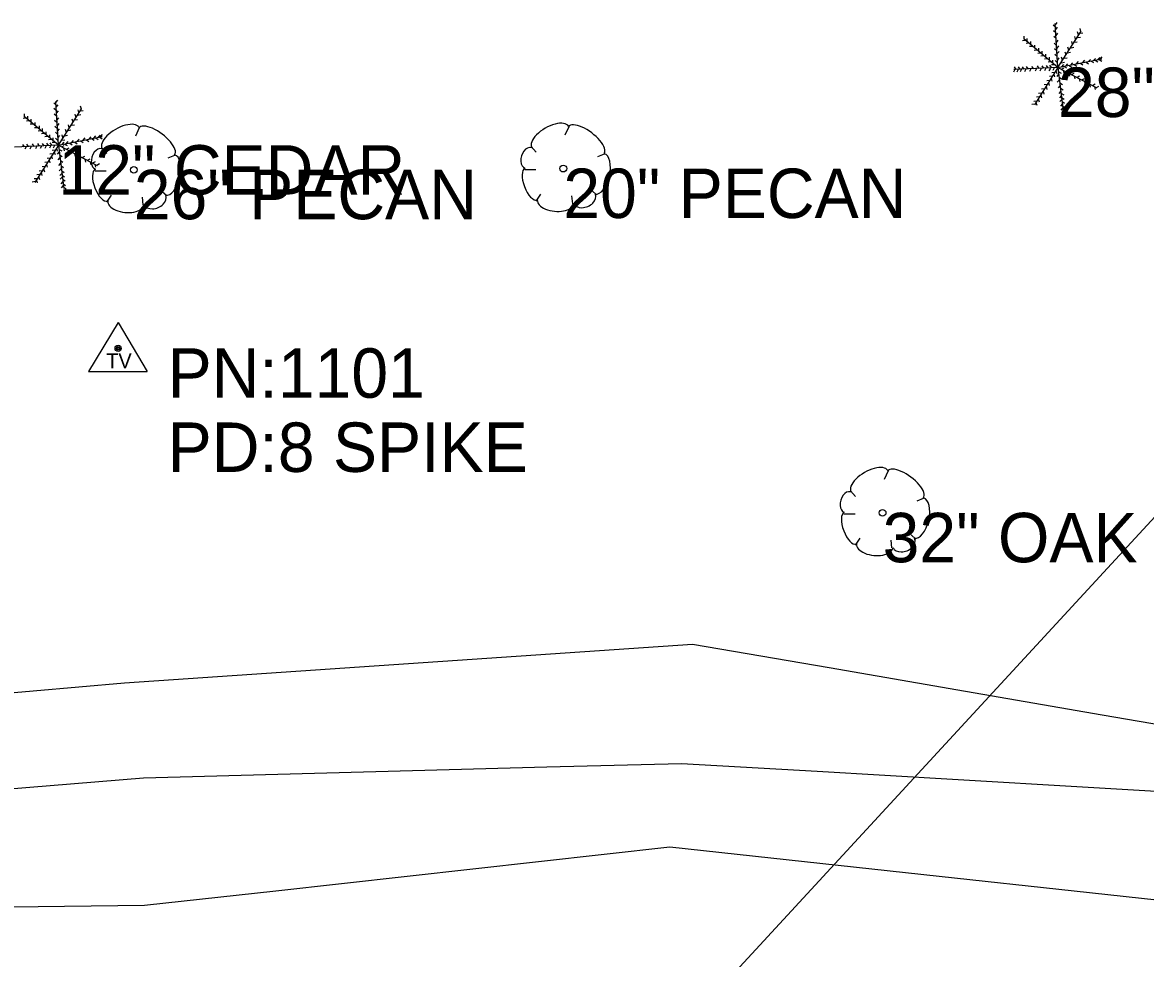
# Model space of a CAD drawing. Extents: x 1930288 to 1941089, y 588389 to 611475.
# Drawn here: x 1930644.9 to 1930758.4, y 598182.1 to 598276.8 of the extents above; entities that cross this region are included whole.
import ezdxf

# ---------------------------------------------------------------- set-up
doc = ezdxf.new("R2010")
doc.units = 0
for name, color, linetype in [('S_DITCHLINE', 7, 'Continuous'), ('S_GAS_UTILITIES', 7, 'Continuous'), ('S_SECONDARY_CTL', 7, 'Continuous'), ('S_SECONDARY_CTL_ANNOT', 7, 'Continuous'), ('S_STREAM', 7, 'Continuous'), ('S_TREE', 7, 'Continuous'), ('S_TREE_ANNOT', 7, 'Continuous')]:
    doc.layers.add(name, color=color, linetype=linetype)

msp = doc.modelspace()

# ---------------------------------------------------------------- linework, layer by layer
at = {"layer": 'S_DITCHLINE'}
msp.add_lwpolyline([(1930873.87, 598182.1), (1930857.41, 598182.4), (1930840.53, 598182.46), (1930823.65, 598182.52), (1930809.32, 598186.54), (1930794.99, 598190.57), (1930780.66, 598194.59), (1930766.34, 598198.62), (1930752.63, 598199.42), (1930738.92, 598200.23), (1930725.22, 598201.03), (1930711.51, 598201.83), (1930697.9, 598201.47), (1930684.3, 598201.1), (1930670.69, 598200.73), (1930657.08, 598200.36), (1930638.19, 598198.83)], dxfattribs=at)
at = {"layer": 'S_GAS_UTILITIES'}
msp.add_line((1930763.56, 598231.34), (1930683.07, 598144.05), dxfattribs=at)
at = {"layer": 'S_SECONDARY_CTL'}
for p, q in [((1930654.53, 598246.45), (1930651.52, 598241.49)), ((1930654.53, 598246.45), (1930657.48, 598241.49)), ((1930651.52, 598241.49), (1930657.48, 598241.49))]:
    msp.add_line(p, q, dxfattribs=at)
for radius in [0.311, 0.183, 0.103]:
    msp.add_circle((1930654.53, 598243.84), radius, dxfattribs=at)
at = {"layer": 'S_STREAM'}
for points in [[(1930906.83, 598185.8), (1930890.27, 598187.32), (1930874.15, 598188.74), (1930858.02, 598190.16), (1930839.57, 598191.65), (1930821.12, 598193.14), (1930807.8, 598195.95), (1930794.49, 598198.75), (1930781.17, 598201.56), (1930767.85, 598204.36), (1930754.04, 598206.75), (1930740.24, 598209.13), (1930726.43, 598211.51), (1930712.62, 598213.9), (1930698.26, 598212.92), (1930683.89, 598211.94), (1930669.53, 598210.96), (1930655.17, 598209.99), (1930636.67, 598208.34)], [(1930795.11, 598181.46), (1930779.97, 598184.46), (1930764.83, 598187.45), (1930751.2, 598188.94), (1930737.57, 598190.42), (1930723.94, 598191.9), (1930710.31, 598193.39), (1930697.04, 598191.91), (1930683.76, 598190.43), (1930670.49, 598188.95), (1930657.21, 598187.47), (1930638.3, 598187.25)]]:
    msp.add_lwpolyline(points, dxfattribs=at)
at = {"layer": 'S_TREE'}
for p, q in [((1930749.33, 598276.32), (1930749.1, 598276.52)), ((1930749.58, 598272.24), (1930749.31, 598276.68)), ((1930749.32, 598276.57), (1930749.51, 598276.8)), ((1930749.35, 598276.09), (1930749.54, 598276.32)), ((1930749.58, 598272.24), (1930746.12, 598275.15)), ((1930746.15, 598275.12), (1930746.15, 598275.42)), ((1930746.47, 598274.87), (1930746.47, 598275.17)), ((1930749.36, 598275.76), (1930749.13, 598275.96)), ((1930749.39, 598275.18), (1930749.16, 598275.38)), ((1930749.38, 598275.49), (1930749.57, 598275.72)), ((1930749.58, 598272.24), (1930751.92, 598275.92)), ((1930751.35, 598275.1), (1930751.27, 598275.39)), ((1930751.54, 598275.29), (1930751.84, 598275.33)), ((1930751.65, 598275.55), (1930751.56, 598275.84)), ((1930751.79, 598275.71), (1930752.08, 598275.76)), ((1930751.9, 598275.89), (1930751.81, 598276.18)), ((1930746.3, 598274.98), (1930746, 598274.94)), ((1930746.64, 598274.71), (1930746.35, 598274.68)), ((1930747.01, 598274.38), (1930746.71, 598274.36)), ((1930746.83, 598274.58), (1930746.83, 598274.88)), ((1930747.46, 598274.01), (1930747.16, 598273.98)), ((1930747.24, 598274.22), (1930747.24, 598274.52)), ((1930747.65, 598273.89), (1930747.65, 598274.19)), ((1930749.41, 598274.52), (1930749.19, 598274.72)), ((1930749.45, 598273.93), (1930749.23, 598274.13)), ((1930749.42, 598274.78), (1930749.61, 598275.01)), ((1930749.49, 598274.21), (1930749.68, 598274.45)), ((1930750.68, 598274.01), (1930750.59, 598274.3)), ((1930750.9, 598274.25), (1930751.19, 598274.3)), ((1930751.06, 598274.58), (1930750.97, 598274.87)), ((1930751.22, 598274.8), (1930751.52, 598274.84)), ((1930747.83, 598273.68), (1930747.53, 598273.66)), ((1930748.16, 598273.41), (1930747.86, 598273.39)), ((1930747.97, 598273.61), (1930747.97, 598273.91)), ((1930748.5, 598273.12), (1930748.2, 598273.09)), ((1930748.34, 598273.31), (1930748.34, 598273.61)), ((1930748.71, 598273), (1930748.71, 598273.3)), ((1930749.06, 598272.69), (1930749.06, 598272.99)), ((1930749.49, 598273.36), (1930749.27, 598273.56)), ((1930749.5, 598272.74), (1930749.28, 598272.94)), ((1930749.5, 598273.65), (1930749.69, 598273.88)), ((1930749.53, 598272.97), (1930749.71, 598273.21)), ((1930749.58, 598272.24), (1930754, 598273.11)), ((1930750.03, 598273), (1930749.94, 598273.28)), ((1930750.21, 598273.2), (1930750.51, 598273.24)), ((1930750.39, 598273.52), (1930750.3, 598273.81)), ((1930750.55, 598273.74), (1930750.84, 598273.78)), ((1930752.09, 598272.76), (1930752.29, 598272.98)), ((1930752.68, 598272.85), (1930752.88, 598273.07)), ((1930752.93, 598272.9), (1930753.18, 598272.74)), ((1930753.16, 598272.95), (1930753.36, 598273.17)), ((1930753.35, 598272.99), (1930753.61, 598272.83)), ((1930753.61, 598273.04), (1930753.81, 598273.26)), ((1930753.76, 598273.05), (1930754.01, 598272.89)), ((1930753.83, 598273.09), (1930754.04, 598273.32)), ((1930745.21, 598272.03), (1930745.08, 598271.76)), ((1930749.58, 598272.24), (1930745.13, 598272.03)), ((1930745.36, 598272.05), (1930745.19, 598272.3)), ((1930745.56, 598272.05), (1930745.43, 598271.79)), ((1930745.75, 598272.08), (1930745.58, 598272.33)), ((1930745.9, 598272.07), (1930745.77, 598271.8)), ((1930746.15, 598272.08), (1930745.98, 598272.33)), ((1930746.32, 598272.09), (1930746.19, 598271.82)), ((1930746.55, 598272.1), (1930746.38, 598272.35)), ((1930746.83, 598272.11), (1930746.7, 598271.84)), ((1930747.12, 598272.12), (1930746.95, 598272.36)), ((1930749.58, 598272.24), (1930747.2, 598268.47)), ((1930747.39, 598272.14), (1930747.26, 598271.87)), ((1930747.67, 598272.15), (1930747.5, 598272.4)), ((1930747.88, 598272.16), (1930747.74, 598271.89)), ((1930748.15, 598272.17), (1930747.98, 598272.42)), ((1930748.35, 598272.18), (1930748.21, 598271.91)), ((1930748.59, 598272.21), (1930748.42, 598272.45)), ((1930748.87, 598272.82), (1930748.57, 598272.8)), ((1930748.81, 598272.19), (1930748.67, 598271.92)), ((1930748.92, 598272.24), (1930748.75, 598272.49)), ((1930749.23, 598272.52), (1930748.93, 598272.5)), ((1930749.25, 598271.74), (1930748.95, 598271.71)), ((1930749.19, 598272.2), (1930749.06, 598271.93)), ((1930749.37, 598271.92), (1930749.45, 598271.63)), ((1930749.58, 598272.24), (1930753.5, 598270.2)), ((1930749.58, 598272.24), (1930750.11, 598267.87)), ((1930749.66, 598271.81), (1930749.91, 598271.66)), ((1930749.91, 598272.06), (1930750.17, 598272.2)), ((1930749.93, 598272.73), (1930750.23, 598272.77)), ((1930749.96, 598272.33), (1930750.16, 598272.55)), ((1930750.09, 598271.96), (1930750.16, 598271.67)), ((1930750.2, 598272.36), (1930750.45, 598272.2)), ((1930750.36, 598272.38), (1930750.56, 598272.61)), ((1930750.39, 598271.83), (1930750.65, 598271.97)), ((1930750.72, 598272.43), (1930750.97, 598272.27)), ((1930750.89, 598272.49), (1930751.09, 598272.71)), ((1930751.23, 598272.55), (1930751.49, 598272.39)), ((1930751.45, 598272.62), (1930751.66, 598272.84)), ((1930751.84, 598272.68), (1930752.09, 598272.52)), ((1930752.42, 598272.78), (1930752.67, 598272.62)), ((1930748.73, 598270.93), (1930748.44, 598270.9)), ((1930748.63, 598270.73), (1930748.7, 598270.44)), ((1930749.01, 598271.38), (1930748.71, 598271.34)), ((1930748.88, 598271.14), (1930748.96, 598270.85)), ((1930749.16, 598271.58), (1930749.24, 598271.29)), ((1930749.64, 598271.56), (1930749.45, 598271.34)), ((1930749.71, 598270.98), (1930749.51, 598270.76)), ((1930749.7, 598271.26), (1930749.95, 598271.1)), ((1930749.78, 598270.69), (1930750.04, 598270.54)), ((1930750.67, 598271.66), (1930750.74, 598271.37)), ((1930750.94, 598271.53), (1930751.21, 598271.67)), ((1930751.21, 598271.38), (1930751.28, 598271.09)), ((1930751.5, 598271.25), (1930751.76, 598271.39)), ((1930751.73, 598271.11), (1930751.8, 598270.82)), ((1930751.98, 598270.99), (1930752.25, 598271.13)), ((1930752.26, 598270.81), (1930752.33, 598270.52)), ((1930752.52, 598270.72), (1930752.78, 598270.86)), ((1930747.92, 598269.64), (1930747.62, 598269.61)), ((1930747.84, 598269.46), (1930747.91, 598269.17)), ((1930748.22, 598270.09), (1930747.92, 598270.06)), ((1930748.08, 598269.84), (1930748.16, 598269.55)), ((1930748.48, 598270.51), (1930748.19, 598270.48)), ((1930748.37, 598270.31), (1930748.44, 598270.01)), ((1930749.79, 598270.42), (1930749.59, 598270.2)), ((1930749.86, 598269.85), (1930749.67, 598269.63)), ((1930749.84, 598270.14), (1930750.1, 598269.99)), ((1930749.92, 598269.63), (1930750.17, 598269.48)), ((1930752.78, 598270.56), (1930752.85, 598270.27)), ((1930753.06, 598270.44), (1930753.33, 598270.58)), ((1930753.27, 598270.31), (1930753.34, 598270.01)), ((1930753.46, 598270.23), (1930753.72, 598270.37)), ((1930648.24, 598268.47), (1930648.01, 598268.67)), ((1930648.49, 598264.39), (1930648.22, 598268.82)), ((1930648.23, 598268.72), (1930648.42, 598268.95)), ((1930648.26, 598268.24), (1930648.45, 598268.47)), ((1930650.81, 598268.04), (1930650.72, 598268.33)), ((1930747.23, 598268.55), (1930746.93, 598268.52)), ((1930747.43, 598268.85), (1930747.13, 598268.82)), ((1930747.35, 598268.71), (1930747.43, 598268.42)), ((1930747.68, 598269.27), (1930747.39, 598269.23)), ((1930747.58, 598269.06), (1930747.66, 598268.77)), ((1930749.93, 598269.4), (1930749.73, 598269.17)), ((1930749.96, 598269.02), (1930749.77, 598268.79)), ((1930750.02, 598268.57), (1930749.83, 598268.34)), ((1930749.95, 598269.2), (1930750.2, 598269.05)), ((1930749.99, 598268.8), (1930750.25, 598268.64)), ((1930750.06, 598268.33), (1930750.31, 598268.17)), ((1930648.49, 598264.39), (1930645.03, 598267.3)), ((1930645.06, 598267.27), (1930645.06, 598267.57)), ((1930645.38, 598267.02), (1930645.38, 598267.32)), ((1930648.27, 598267.9), (1930648.04, 598268.1)), ((1930648.3, 598267.33), (1930648.07, 598267.53)), ((1930648.29, 598267.64), (1930648.48, 598267.87)), ((1930648.49, 598264.39), (1930650.83, 598268.07)), ((1930650.26, 598267.25), (1930650.18, 598267.53)), ((1930650.45, 598267.43), (1930650.75, 598267.48)), ((1930650.56, 598267.7), (1930650.47, 598267.98)), ((1930650.7, 598267.86), (1930650.99, 598267.9)), ((1930750.07, 598268.15), (1930749.87, 598267.92)), ((1930750.1, 598267.99), (1930750.35, 598267.83)), ((1930645.21, 598267.13), (1930644.91, 598267.09)), ((1930645.55, 598266.85), (1930645.26, 598266.83)), ((1930645.92, 598266.53), (1930645.62, 598266.51)), ((1930645.74, 598266.73), (1930645.74, 598267.03)), ((1930646.37, 598266.16), (1930646.07, 598266.13)), ((1930646.15, 598266.37), (1930646.15, 598266.67)), ((1930646.56, 598266.04), (1930646.56, 598266.34)), ((1930646.88, 598265.76), (1930646.88, 598266.06)), ((1930648.32, 598266.67), (1930648.1, 598266.87)), ((1930648.36, 598266.08), (1930648.14, 598266.28)), ((1930648.33, 598266.93), (1930648.52, 598267.16)), ((1930648.4, 598266.36), (1930648.58, 598266.59)), ((1930649.59, 598266.16), (1930649.5, 598266.45)), ((1930649.81, 598266.4), (1930650.1, 598266.45)), ((1930649.97, 598266.73), (1930649.88, 598267.02)), ((1930650.13, 598266.94), (1930650.43, 598266.99)), ((1930656.67, 598266.15), (1930656.28, 598265.3)), ((1930700.11, 598266.26), (1930699.72, 598265.41)), ((1930646.74, 598265.83), (1930646.44, 598265.8)), ((1930647.07, 598265.56), (1930646.77, 598265.54)), ((1930647.41, 598265.27), (1930647.11, 598265.24)), ((1930647.25, 598265.45), (1930647.25, 598265.75)), ((1930647.78, 598264.97), (1930647.48, 598264.94)), ((1930647.62, 598265.15), (1930647.62, 598265.45)), ((1930647.97, 598264.83), (1930647.97, 598265.13)), ((1930648.4, 598265.51), (1930648.18, 598265.71)), ((1930648.41, 598264.89), (1930648.19, 598265.09)), ((1930648.41, 598265.79), (1930648.6, 598266.03)), ((1930648.44, 598265.12), (1930648.62, 598265.36)), ((1930648.49, 598264.39), (1930652.91, 598265.25)), ((1930648.84, 598264.88), (1930649.14, 598264.92)), ((1930648.94, 598265.14), (1930648.85, 598265.43)), ((1930649.12, 598265.34), (1930649.42, 598265.39)), ((1930649.3, 598265.67), (1930649.21, 598265.96)), ((1930649.46, 598265.89), (1930649.75, 598265.93)), ((1930650.36, 598264.76), (1930650.57, 598264.99)), ((1930651, 598264.91), (1930651.2, 598265.13)), ((1930651.33, 598264.93), (1930651.58, 598264.77)), ((1930651.59, 598265), (1930651.79, 598265.22)), ((1930651.84, 598265.05), (1930652.09, 598264.89)), ((1930652.07, 598265.1), (1930652.27, 598265.32)), ((1930652.26, 598265.14), (1930652.52, 598264.98)), ((1930652.52, 598265.19), (1930652.72, 598265.41)), ((1930652.67, 598265.19), (1930652.92, 598265.03)), ((1930652.74, 598265.24), (1930652.95, 598265.46)), ((1930648.49, 598264.39), (1930644.04, 598264.18)), ((1930645.06, 598264.22), (1930644.89, 598264.47)), ((1930645.23, 598264.23), (1930645.1, 598263.97)), ((1930645.46, 598264.25), (1930645.29, 598264.5)), ((1930645.74, 598264.26), (1930645.61, 598263.99)), ((1930646.03, 598264.26), (1930645.86, 598264.51)), ((1930648.49, 598264.39), (1930646.11, 598260.61)), ((1930646.3, 598264.29), (1930646.17, 598264.02)), ((1930646.58, 598264.3), (1930646.41, 598264.55)), ((1930646.79, 598264.3), (1930646.65, 598264.04)), ((1930647.06, 598264.32), (1930646.89, 598264.56)), ((1930647.26, 598264.33), (1930647.12, 598264.06)), ((1930647.5, 598264.35), (1930647.33, 598264.6)), ((1930647.72, 598264.34), (1930647.58, 598264.07)), ((1930647.83, 598264.39), (1930647.66, 598264.64)), ((1930648.14, 598264.67), (1930647.84, 598264.65)), ((1930648.16, 598263.89), (1930647.86, 598263.86)), ((1930648.1, 598264.35), (1930647.97, 598264.08)), ((1930648.28, 598264.07), (1930648.36, 598263.78)), ((1930648.49, 598264.39), (1930652.41, 598262.34)), ((1930648.49, 598264.39), (1930649.02, 598260.02)), ((1930648.57, 598263.96), (1930648.82, 598263.81)), ((1930648.82, 598264.21), (1930649.08, 598264.35)), ((1930648.87, 598264.47), (1930649.07, 598264.7)), ((1930649, 598264.11), (1930649.07, 598263.82)), ((1930649.11, 598264.5), (1930649.36, 598264.34)), ((1930649.27, 598264.53), (1930649.47, 598264.75)), ((1930649.3, 598263.98), (1930649.56, 598264.12)), ((1930649.58, 598263.81), (1930649.65, 598263.52)), ((1930649.63, 598264.58), (1930649.88, 598264.42)), ((1930649.8, 598264.63), (1930650, 598264.86)), ((1930649.85, 598263.68), (1930650.12, 598263.82)), ((1930650.14, 598264.7), (1930650.4, 598264.54)), ((1930650.75, 598264.83), (1930651, 598264.67)), ((1930652.87, 598264.13), (1930653.37, 598263.55)), ((1930696.31, 598264.25), (1930696.82, 598263.67)), ((1930647.39, 598262.66), (1930647.1, 598262.63)), ((1930647.64, 598263.08), (1930647.35, 598263.04)), ((1930647.54, 598262.88), (1930647.61, 598262.59)), ((1930647.92, 598263.52), (1930647.62, 598263.49)), ((1930647.79, 598263.29), (1930647.87, 598263)), ((1930648.07, 598263.73), (1930648.15, 598263.44)), ((1930648.55, 598263.71), (1930648.36, 598263.49)), ((1930648.62, 598263.13), (1930648.42, 598262.9)), ((1930648.61, 598263.41), (1930648.86, 598263.25)), ((1930648.69, 598262.84), (1930648.95, 598262.68)), ((1930650.12, 598263.53), (1930650.19, 598263.24)), ((1930650.41, 598263.39), (1930650.67, 598263.53)), ((1930650.64, 598263.26), (1930650.71, 598262.97)), ((1930650.89, 598263.14), (1930651.16, 598263.28)), ((1930651.17, 598262.96), (1930651.24, 598262.67)), ((1930651.43, 598262.87), (1930651.69, 598263.01)), ((1930651.69, 598262.7), (1930651.76, 598262.41)), ((1930651.97, 598262.59), (1930652.24, 598262.73)), ((1930660.23, 598263.36), (1930659.57, 598263.09)), ((1930703.68, 598263.47), (1930703.02, 598263.2)), ((1930646.83, 598261.79), (1930646.53, 598261.75)), ((1930646.75, 598261.61), (1930646.82, 598261.32)), ((1930647.13, 598262.24), (1930646.83, 598262.21)), ((1930646.99, 598261.99), (1930647.07, 598261.7)), ((1930647.28, 598262.45), (1930647.35, 598262.16)), ((1930648.7, 598262.57), (1930648.5, 598262.34)), ((1930648.77, 598262), (1930648.58, 598261.78)), ((1930648.84, 598261.54), (1930648.64, 598261.32)), ((1930648.75, 598262.29), (1930649.01, 598262.14)), ((1930648.83, 598261.78), (1930649.08, 598261.63)), ((1930652.18, 598262.45), (1930652.25, 598262.16)), ((1930652.21, 598261.81), (1930653.33, 598261.81)), ((1930652.37, 598262.38), (1930652.63, 598262.52)), ((1930695.65, 598261.92), (1930696.78, 598261.92)), ((1930646.14, 598260.7), (1930645.84, 598260.66)), ((1930646.34, 598261), (1930646.04, 598260.97)), ((1930646.26, 598260.86), (1930646.34, 598260.57)), ((1930646.59, 598261.41), (1930646.3, 598261.38)), ((1930646.49, 598261.21), (1930646.57, 598260.92)), ((1930648.87, 598261.16), (1930648.68, 598260.94)), ((1930648.93, 598260.72), (1930648.74, 598260.49)), ((1930648.86, 598261.35), (1930649.11, 598261.19)), ((1930648.9, 598260.94), (1930649.16, 598260.79)), ((1930648.97, 598260.48), (1930649.22, 598260.32)), ((1930648.98, 598260.3), (1930648.78, 598260.07)), ((1930649.01, 598260.14), (1930649.26, 598259.98)), ((1930653.37, 598258.63), (1930653.84, 598259.33)), ((1930659.46, 598259.25), (1930658.99, 598259.68)), ((1930696.82, 598258.74), (1930697.28, 598259.44)), ((1930700.5, 598258.47), (1930700.42, 598259.25)), ((1930702.9, 598259.36), (1930702.44, 598259.79)), ((1930657.05, 598258.36), (1930656.98, 598259.14)), ((1930732.4, 598231.45), (1930732.01, 598230.59)), ((1930728.6, 598229.43), (1930729.11, 598228.85)), ((1930735.96, 598228.66), (1930735.31, 598228.39)), ((1930727.94, 598227.11), (1930729.07, 598227.11)), ((1930729.11, 598223.93), (1930729.57, 598224.63)), ((1930732.79, 598223.66), (1930732.71, 598224.43)), ((1930735.19, 598224.55), (1930734.72, 598224.98))]:
    msp.add_line(p, q, dxfattribs=at)
for centre in [(1930656.11, 598261.9), (1930699.55, 598262.02), (1930731.84, 598227.2)]:
    msp.add_circle(centre, 0.341, dxfattribs=at)
for centre, major_axis, ratio, start_param, end_param in [((1930654.77, 598265.11), (1.86, 1.08), 0.471018, 0, 3.141593), ((1930658.43, 598264.78), (-1.81, 1.36), 0.405113, 3.141593, 6.283186), ((1930698.22, 598265.22), (1.86, 1.08), 0.471018, 0, 3.141593), ((1930701.87, 598264.9), (-1.81, 1.36), 0.405113, 3.141593, 6.283186), ((1930652.54, 598262.99), (0.31, 1.03), 0.646762, 0, 3.141593), ((1930695.98, 598263.1), (0.31, 1.03), 0.646762, 0, 3.141593), ((1930659.78, 598261.37), (0.46, 2.04), 0.482994, 3.141593, 6.283185), ((1930703.23, 598261.49), (0.46, 2.04), 0.482994, 3.141593, 6.283185), ((1930652.84, 598260.34), (-0.61, 1.6), 0.420543, 6.283185, 9.424777), ((1930696.29, 598260.45), (-0.61, 1.6), 0.420543, 6.283185, 9.424777), ((1930658.26, 598258.85), (1.09, 0.46), 0.711534, 3.141592, 6.283185), ((1930701.7, 598258.97), (1.09, 0.46), 0.711534, 3.141592, 6.283185), ((1930655.3, 598258.56), (-1.83, 0.19), 0.529943, 0, 3.141593), ((1930698.75, 598258.67), (-1.83, 0.19), 0.529943, 0, 3.141593), ((1930730.51, 598230.4), (1.86, 1.08), 0.471018, 0, 3.141593), ((1930734.16, 598230.08), (-1.81, 1.36), 0.405113, 3.141593, 6.283186), ((1930728.27, 598228.29), (0.31, 1.03), 0.646762, 0, 3.141593), ((1930735.52, 598226.67), (0.46, 2.04), 0.482994, 3.141593, 6.283185), ((1930728.58, 598225.64), (-0.61, 1.6), 0.420543, 6.283185, 9.424777), ((1930731.04, 598223.86), (-1.83, 0.19), 0.529943, 0, 3.141593), ((1930733.99, 598224.15), (1.09, 0.46), 0.711534, 3.141592, 6.283185)]:
    msp.add_ellipse(centre, major_axis=major_axis, ratio=ratio, start_param=start_param, end_param=end_param, dxfattribs=at)

# ---------------------------------------------------------------- texts
at = {"layer": 'S_SECONDARY_CTL'}
msp.add_text('TV', height=1.5, rotation=360, dxfattribs=at).set_placement((1930653.33, 598241.82))
at = {"layer": 'S_SECONDARY_CTL_ANNOT'}
for s, p in [('PN:1101', (1930659.53, 598238.84)), ('PD:8 SPIKE', (1930659.53, 598231.34))]:
    msp.add_text(s, height=5, dxfattribs=at).set_placement(p)
at = {"layer": 'S_TREE_ANNOT'}
for s, p in [('28" CEDAR', (1930749.58, 598267.24)), ('12" CEDAR', (1930648.49, 598259.39)), ('26" PECAN', (1930656.11, 598256.9)), ('20" PECAN', (1930699.55, 598257.02)), ('32" OAK', (1930731.84, 598222.2))]:
    msp.add_text(s, height=5, dxfattribs=at).set_placement(p)

doc.saveas('drawing.dxf')
